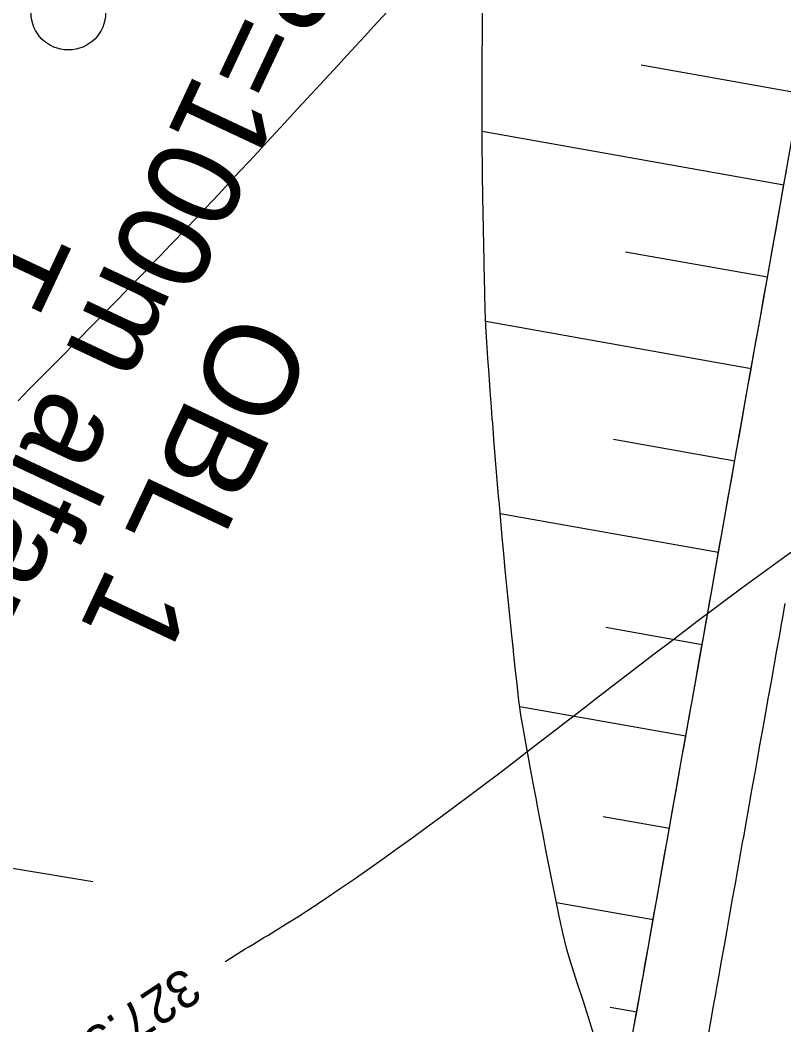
# Model space of a CAD drawing. Extents: x -564043 to -563833, y -1163561 to -1163412.
# Drawn here: x -563941.23 to -563931, y -1163501.37 to -1163487.91 of the extents above; entities that cross this region are included whole.
import ezdxf

# ---------------------------------------------------------------- set-up
doc = ezdxf.new("R2010")
doc.units = 0
for name, color, linetype in [('_popis staničení PH1', 7, 'Continuous'), ('_popis staničení T1', 7, 'Continuous'), ('Line', 7, 'Continuous'), ('Vrstva 24', 7, 'Continuous'), ('Vrstva 25', 7, 'Continuous'), ('Vrstva 26', 7, 'Continuous')]:
    doc.layers.add(name, color=color, linetype=linetype)

msp = doc.modelspace()

# ---------------------------------------------------------------- linework, layer by layer
for points in [[(-563933.061, -1163501.709), (-563932.976, -1163501.232), (-563932.886, -1163500.725), (-563932.71, -1163499.74), (-563932.535, -1163498.756), (-563932.36, -1163497.771), (-563932.185, -1163496.786), (-563932.01, -1163495.802), (-563931.835, -1163494.817), (-563931.659, -1163493.833), (-563931.484, -1163492.848), (-563931.404, -1163492.395), (-563931.309, -1163491.864), (-563931.134, -1163490.879), (-563930.959, -1163489.895), (-563930.784, -1163488.91), (-563930.608, -1163487.926), (-563930.509, -1163487.367)], [(-563933.543, -1163501.505), (-563933.617, -1163501.277), (-563933.69, -1163501.049), (-563933.762, -1163500.822), (-563933.835, -1163500.594), (-563933.847, -1163500.554), (-563933.906, -1163500.366), (-563933.962, -1163500.141), (-563934.008, -1163499.918), (-563934.053, -1163499.695), (-563934.094, -1163499.494), (-563934.098, -1163499.473), (-563934.142, -1163499.25), (-563934.186, -1163499.027), (-563934.23, -1163498.804), (-563934.273, -1163498.582), (-563934.299, -1163498.442), (-563934.315, -1163498.359), (-563934.357, -1163498.137), (-563934.398, -1163497.915), (-563934.439, -1163497.693), (-563934.479, -1163497.471), (-563934.494, -1163497.391), (-563934.519, -1163497.249), (-563934.548, -1163497.029), (-563934.573, -1163496.809), (-563934.597, -1163496.59), (-563934.621, -1163496.371), (-563934.623, -1163496.353), (-563934.644, -1163496.152), (-563934.666, -1163495.933), (-563934.689, -1163495.714), (-563934.71, -1163495.495), (-563934.727, -1163495.318), (-563934.731, -1163495.277), (-563934.752, -1163495.058), (-563934.772, -1163494.84), (-563934.792, -1163494.621), (-563934.811, -1163494.403), (-563934.821, -1163494.286), (-563934.83, -1163494.185), (-563934.848, -1163493.967), (-563934.866, -1163493.749), (-563934.883, -1163493.531), (-563934.9, -1163493.313), (-563934.905, -1163493.255), (-563934.917, -1163493.095), (-563934.932, -1163492.877), (-563934.948, -1163492.66), (-563934.963, -1163492.442), (-563934.977, -1163492.227), (-563934.977, -1163492.225), (-563934.991, -1163492.007), (-563934.999, -1163491.791), (-563935.006, -1163491.575), (-563935.011, -1163491.359), (-563935.015, -1163491.204), (-563935.016, -1163491.143), (-563935.021, -1163490.927), (-563935.025, -1163490.712), (-563935.029, -1163490.496), (-563935.032, -1163490.281), (-563935.033, -1163490.185), (-563935.035, -1163490.065), (-563935.037, -1163489.85), (-563935.039, -1163489.635), (-563935.04, -1163489.42), (-563935.041, -1163489.205), (-563935.041, -1163489.168), (-563935.041, -1163488.99), (-563935.041, -1163488.775), (-563935.04, -1163488.56), (-563935.039, -1163488.345), (-563935.037, -1163488.153), (-563935.037, -1163488.131), (-563935.035, -1163487.916), (-563935.032, -1163487.702)], [(-563933.003, -1163501.386), (-563932.966, -1163501.178), (-563932.929, -1163500.97), (-563932.892, -1163500.762), (-563932.886, -1163500.725), (-563932.855, -1163500.553), (-563932.818, -1163500.345), (-563932.781, -1163500.137), (-563932.744, -1163499.928), (-563932.71, -1163499.74), (-563932.707, -1163499.72), (-563932.67, -1163499.512), (-563932.633, -1163499.303), (-563932.596, -1163499.095), (-563932.559, -1163498.887), (-563932.535, -1163498.756), (-563932.522, -1163498.679), (-563932.485, -1163498.47), (-563932.447, -1163498.262), (-563932.41, -1163498.054), (-563932.373, -1163497.845), (-563932.36, -1163497.771), (-563932.336, -1163497.637), (-563932.299, -1163497.429), (-563932.262, -1163497.22), (-563932.225, -1163497.012), (-563932.188, -1163496.804), (-563932.185, -1163496.786), (-563932.151, -1163496.596), (-563932.114, -1163496.387), (-563932.077, -1163496.179), (-563932.04, -1163495.971), (-563932.01, -1163495.802), (-563932.003, -1163495.762), (-563931.966, -1163495.554), (-563931.929, -1163495.346), (-563931.892, -1163495.137), (-563931.855, -1163494.929), (-563931.835, -1163494.817), (-563931.817, -1163494.721), (-563931.78, -1163494.513), (-563931.743, -1163494.304), (-563931.706, -1163494.096), (-563931.669, -1163493.888), (-563931.659, -1163493.833), (-563931.632, -1163493.679), (-563931.595, -1163493.471), (-563931.558, -1163493.263), (-563931.521, -1163493.054), (-563931.484, -1163492.848), (-563931.484, -1163492.846), (-563931.447, -1163492.638), (-563931.41, -1163492.43), (-563931.373, -1163492.221), (-563931.336, -1163492.013), (-563931.309, -1163491.864), (-563931.299, -1163491.805), (-563931.262, -1163491.596), (-563931.224, -1163491.388), (-563931.187, -1163491.18), (-563931.15, -1163490.971), (-563931.134, -1163490.879), (-563931.113, -1163490.763), (-563931.076, -1163490.555), (-563931.039, -1163490.347), (-563931.002, -1163490.138), (-563930.965, -1163489.93)], [(-563933.003, -1163501.386), (-563932.966, -1163501.178), (-563932.929, -1163500.97), (-563932.892, -1163500.762), (-563932.886, -1163500.725), (-563932.855, -1163500.553), (-563932.818, -1163500.345), (-563932.781, -1163500.137), (-563932.744, -1163499.928), (-563932.71, -1163499.74), (-563932.707, -1163499.72), (-563932.67, -1163499.512), (-563932.633, -1163499.303), (-563932.596, -1163499.095), (-563932.559, -1163498.887), (-563932.535, -1163498.756), (-563932.522, -1163498.679), (-563932.485, -1163498.47), (-563932.447, -1163498.262), (-563932.41, -1163498.054), (-563932.373, -1163497.845), (-563932.36, -1163497.771), (-563932.336, -1163497.637), (-563932.299, -1163497.429), (-563932.262, -1163497.22), (-563932.225, -1163497.012), (-563932.188, -1163496.804), (-563932.185, -1163496.786), (-563932.151, -1163496.596), (-563932.114, -1163496.387), (-563932.077, -1163496.179), (-563932.04, -1163495.971), (-563932.01, -1163495.802), (-563932.003, -1163495.762), (-563931.966, -1163495.554), (-563931.929, -1163495.346), (-563931.892, -1163495.137), (-563931.855, -1163494.929), (-563931.835, -1163494.817), (-563931.817, -1163494.721), (-563931.78, -1163494.513), (-563931.743, -1163494.304), (-563931.706, -1163494.096), (-563931.669, -1163493.888), (-563931.659, -1163493.833), (-563931.632, -1163493.679), (-563931.595, -1163493.471), (-563931.558, -1163493.263), (-563931.521, -1163493.054), (-563931.484, -1163492.848), (-563931.484, -1163492.846), (-563931.447, -1163492.638), (-563931.41, -1163492.43), (-563931.373, -1163492.221), (-563931.336, -1163492.013), (-563931.309, -1163491.864), (-563931.299, -1163491.805), (-563931.262, -1163491.596), (-563931.224, -1163491.388), (-563931.187, -1163491.18), (-563931.15, -1163490.971), (-563931.134, -1163490.879), (-563931.113, -1163490.763), (-563931.076, -1163490.555), (-563931.039, -1163490.347), (-563931.002, -1163490.138), (-563930.965, -1163489.93)], [(-563940.257, -1163499.457), (-563955.795, -1163496.878), (-563958.985, -1163493.039)], [(-563932.019, -1163501.562), (-563931.982, -1163501.353), (-563931.945, -1163501.145), (-563931.908, -1163500.937), (-563931.901, -1163500.9), (-563931.871, -1163500.728), (-563931.834, -1163500.52), (-563931.796, -1163500.312), (-563931.759, -1163500.103), (-563931.726, -1163499.915), (-563931.722, -1163499.895), (-563931.685, -1163499.687), (-563931.648, -1163499.479), (-563931.611, -1163499.27), (-563931.574, -1163499.062), (-563931.551, -1163498.931), (-563931.537, -1163498.854), (-563931.5, -1163498.645), (-563931.463, -1163498.437), (-563931.426, -1163498.229), (-563931.389, -1163498.02), (-563931.376, -1163497.946), (-563931.352, -1163497.812), (-563931.315, -1163497.604), (-563931.278, -1163497.396), (-563931.241, -1163497.187), (-563931.204, -1163496.979), (-563931.2, -1163496.962), (-563931.166, -1163496.771), (-563931.129, -1163496.562), (-563931.092, -1163496.354), (-563931.055, -1163496.146), (-563931.025, -1163495.977), (-563931.018, -1163495.937), (-563930.981, -1163495.729)]]:
    msp.add_lwpolyline(points)
at = {"layer": '_popis staničení T1'}
msp.add_circle((-563940.586, -1163487.812), 0.5, dxfattribs=at)
at = {"layer": 'Line'}
for p, q in [((-563932.909, -1163488.513), (-563930.78, -1163488.892)), ((-563930.999, -1163490.123), (-563935.04, -1163489.404)), ((-563933.122, -1163491.015), (-563931.218, -1163491.353)), ((-563931.437, -1163492.584), (-563934.993, -1163491.951)), ((-563933.281, -1163493.526), (-563931.656, -1163493.815)), ((-563931.875, -1163495.045), (-563934.801, -1163494.525)), ((-563933.386, -1163496.046), (-563932.094, -1163496.276)), ((-563932.313, -1163497.507), (-563934.537, -1163497.111)), ((-563933.418, -1163498.58), (-563932.532, -1163498.737)), ((-563932.751, -1163499.968), (-563934.044, -1163499.738)), ((-563933.326, -1163501.135), (-563932.97, -1163501.199))]:
    msp.add_line(p, q, dxfattribs=at)
at = {"layer": 'Vrstva 24'}
for points in [[(-563941.26, -1163493.011), (-563939.004, -1163490.701), (-563935.168, -1163486.585), (-563933.596, -1163484.774), (-563933.04, -1163483.789), (-563932.447, -1163481.939), (-563932.386, -1163481.578), (-563932.335, -1163479.091), (-563932.359, -1163478.881), (-563932.37, -1163478.699), (-563932.356, -1163477.982), (-563932.286, -1163477.265), (-563932.226, -1163476.548), (-563932.242, -1163475.831), (-563932.273, -1163475.745), (-563932.328, -1163475.651), (-563935.188, -1163471.035), (-563938.348, -1163465.934), (-563938.454, -1163465.786), (-563938.858, -1163465.285), (-563944.231, -1163458.582)], [(-563939.075, -1163507.623), (-563938.225, -1163507.164), (-563937.324, -1163506.641), (-563936.436, -1163506.097), (-563935.549, -1163505.552), (-563934.649, -1163505.03), (-563930.625, -1163502.906), (-563929.451, -1163502.347), (-563928.196, -1163501.635), (-563924.955, -1163499.225), (-563920.602, -1163495.57), (-563920.316, -1163495.267), (-563915.394, -1163488.268), (-563914.823, -1163487.183), (-563914.579, -1163485.87), (-563914.81, -1163484.102), (-563915.208, -1163482.646), (-563915.847, -1163480.252), (-563916.025, -1163479.9), (-563916.675, -1163479.113), (-563917.077, -1163478.648)], [(-563942.475, -1163518.079), (-563940.112, -1163517.387), (-563935.904, -1163515.974), (-563933.959, -1163515.268), (-563929.245, -1163513.665), (-563925.032, -1163512.173), (-563922.819, -1163511.166), (-563919.003, -1163509.075), (-563915.156, -1163506.928), (-563914.035, -1163506.214), (-563913.139, -1163505.478), (-563911.421, -1163503.905), (-563910.565, -1163503.115), (-563909.689, -1163502.349), (-563908.668, -1163501.532), (-563907.622, -1163500.746), (-563906.572, -1163499.965), (-563905.922, -1163499.466)]]:
    msp.add_spline(points, degree=3, dxfattribs=at)
at = {"layer": 'Vrstva 26'}
for points in [[(-563938.486, -1163500.528), (-563938.463, -1163500.513), (-563937.665, -1163500.022), (-563936.97, -1163499.566), (-563930.777, -1163494.949), (-563928.884, -1163493.45), (-563928.656, -1163493.192), (-563928.195, -1163492.447), (-563924.372, -1163485.735), (-563923.788, -1163484.5), (-563923.604, -1163483.639), (-563923.611, -1163481.604), (-563923.712, -1163481.017), (-563924.518, -1163478.475), (-563924.689, -1163477.919), (-563924.751, -1163477.798), (-563925.518, -1163476.583), (-563926.306, -1163475.384), (-563927.092, -1163474.184), (-563927.851, -1163472.968), (-563928.532, -1163471.813), (-563929.192, -1163470.645), (-563929.849, -1163469.476), (-563930.525, -1163468.317), (-563930.688, -1163468.07), (-563931.156, -1163467.471), (-563931.276, -1163467.321)], [(-563940.525, -1163513.198), (-563938.9, -1163512.504), (-563932.611, -1163509.84), (-563931.885, -1163509.567), (-563930.901, -1163509.188), (-563926.659, -1163507.216), (-563923.334, -1163505.549), (-563921.652, -1163504.643), (-563920.105, -1163503.651), (-563917.012, -1163501.201), (-563913.048, -1163497.944), (-563912.649, -1163497.606), (-563912.385, -1163497.353), (-563911.289, -1163496.159), (-563908.991, -1163493.383), (-563906.775, -1163490.536), (-563906.699, -1163490.433)]]:
    msp.add_spline(points, degree=3, dxfattribs=at)

# ---------------------------------------------------------------- texts
at = {"layer": '_popis staničení PH1'}
for s, p in [('R=100m alfa=6.44%%d', (-563937.947, -1163486.606)), ('  T=5.63', (-563941.27, -1163489.567)), ('OBL 1', (-563938.426, -1163491.746))]:
    msp.add_text(s, height=1.25, rotation=244.8543, dxfattribs=at).set_placement(p)
at = {"layer": 'Vrstva 25'}
msp.add_text('327.50', height=0.5, rotation=213.3036, dxfattribs=at).set_placement((-563939.031, -1163500.587))

doc.saveas('drawing.dxf')
